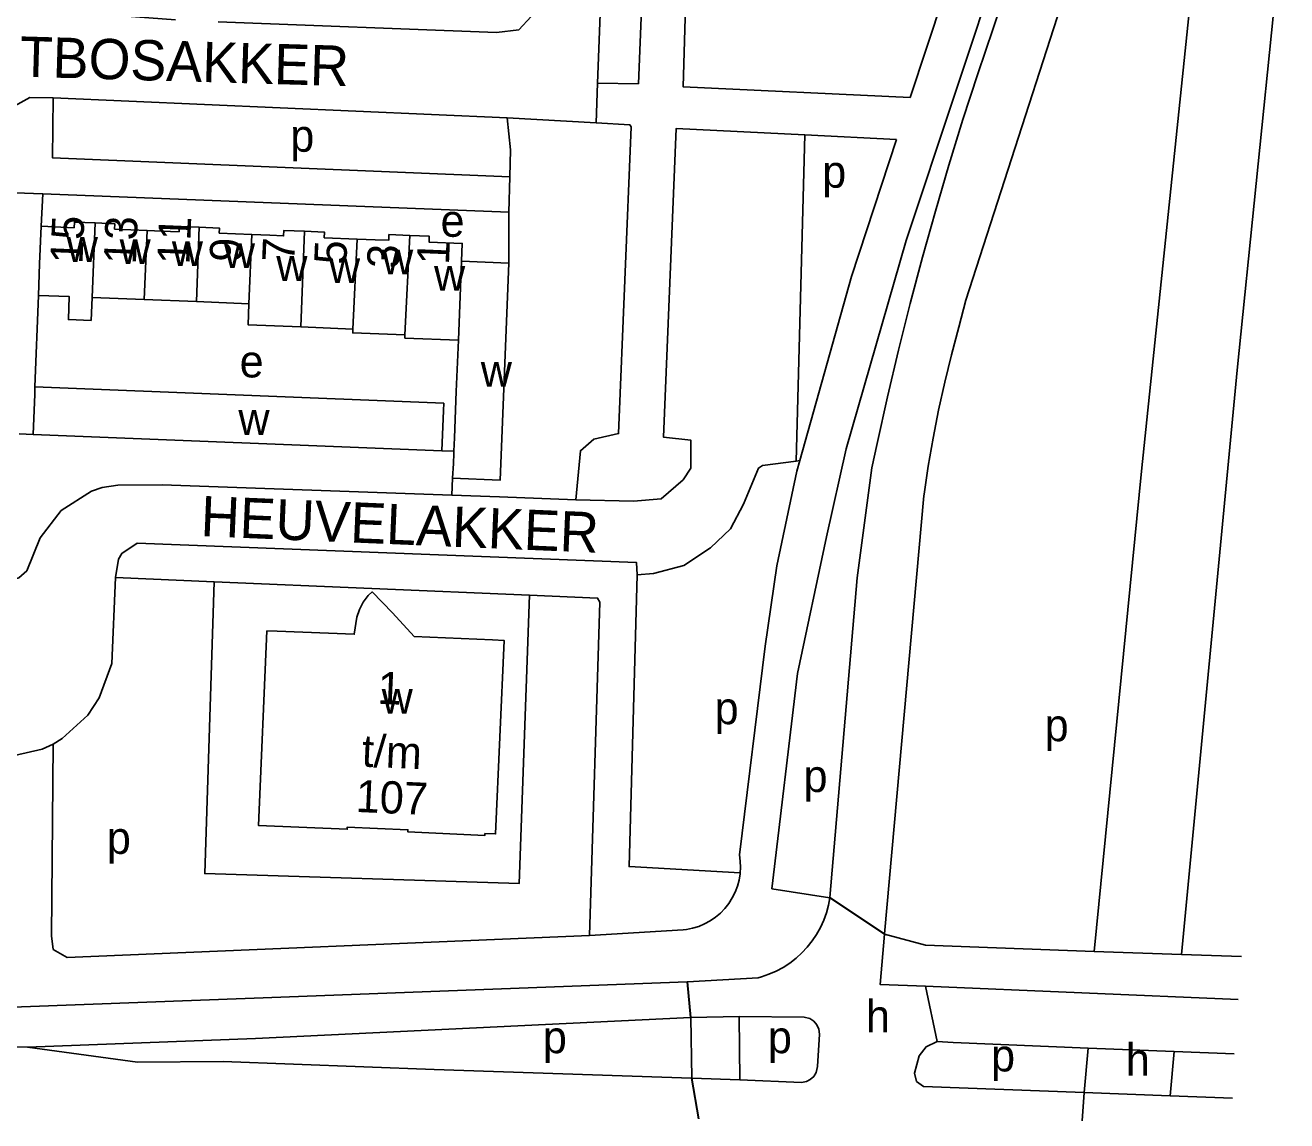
# Model space of a CAD drawing. Extents: x 159675 to 162108, y 386471 to 388472.
# Drawn here: x 161786.5 to 161943, y 386511.2 to 386647.1 of the extents above; entities that cross this region are included whole.
import ezdxf

# ---------------------------------------------------------------- set-up
doc = ezdxf.new("R2010")
doc.units = 0
for name, color, linetype in [('BLT_Basislijn', 7, 'Continuous'), ('BLT_Bebouwing', 7, 'Continuous'), ('BLT_Centroide', 7, 'Continuous'), ('BLT_Huisnummer', 7, 'Continuous'), ('BLT_Huisnummer_ tussenligend', 7, 'Continuous'), ('BLT_Huisnummer_reeks', 7, 'Continuous'), ('BLT_Onderverdeling_panden', 7, 'Continuous'), ('BLT_Straatnaam', 7, 'Continuous'), ('BLT_Vlakafsluiter', 7, 'Continuous')]:
    doc.layers.add(name, color=color, linetype=linetype)

msp = doc.modelspace()

# ---------------------------------------------------------------- linework, layer by layer
at = {"layer": 'BLT_Basislijn'}
for p, q in [((161859.4, 386689.5), (161857.47, 386639.94)), ((161943.04, 386664.85), (161936.89, 386604.32)), ((161904.47, 386662.94), (161896.31, 386638.15)), ((161908.9, 386653.63), (161906.59, 386646.72)), ((161857.33, 386635.03), (161857.47, 386639.94)), ((161846.28, 386635.63), (161789.92, 386638.11)), ((161857.33, 386635.03), (161846.28, 386635.63)), ((161882.16, 386593.06), (161883.24, 386633.54)), ((161894.59, 386632.96), (161883.24, 386633.54)), ((161759.37, 386627.34), (161788.65, 386626.22)), ((161846.48, 386623.96), (161846.61, 386628.31)), ((161788.44, 386622.19), (161788.65, 386626.22)), ((161788.65, 386626.22), (161846.48, 386623.96)), ((161846.5, 386617.63), (161846.48, 386623.96)), ((161787.67, 386602.26), (161788.09, 386613.62)), ((161936.89, 386604.32), (161929.99, 386531.84)), ((161785.72, 386596.45), (161787.43, 386596.36)), ((161838.18, 386594.33), (161839.66, 386594.27)), ((161882.16, 386593.06), (161882.59, 386593.12)), ((161882.59, 386593.12), (161882.22, 386591.81)), ((161839.41, 386588.84), (161839.51, 386590.94)), ((161925.02, 386591.81), (161919.12, 386532.23)), ((161897.99, 386588.74), (161893.13, 386534.42)), ((161797.66, 386578.61), (161809.91, 386578.09)), ((161849.05, 386576.41), (161809.91, 386578.09)), ((161879.13, 386539.98), (161886.32, 386538.87)), ((161868.11, 386534.89), (161856.51, 386534.19)), ((161893.13, 386534.42), (161893.13, 386534.37)), ((161919.12, 386532.23), (161929.99, 386531.84)), ((161929.99, 386531.84), (161937.43, 386531.57)), ((161877.43, 386528.96), (161868.67, 386528.44)), ((161898.2, 386527.9), (161937.02, 386526.27)), ((161869.09, 386524.04), (161875.06, 386524.13)), ((161869.19, 386516.5), (161869.09, 386524.04)), ((161875.14, 386516.27), (161875.06, 386524.13)), ((161773.01, 386520.5), (161786.75, 386520.36)), ((161901.65, 386520.9), (161918.38, 386520.23)), ((161918.38, 386520.23), (161917.91, 386514.7)), ((161918.38, 386520.23), (161929.06, 386519.8)), ((161929.06, 386519.8), (161928.57, 386514.3)), ((161929.06, 386519.8), (161936.5, 386519.51)), ((161875.14, 386516.27), (161869.19, 386516.5)), ((161917.91, 386514.7), (161928.57, 386514.3)), ((161928.57, 386514.3), (161936.29, 386514.01))]:
    msp.add_line(p, q, dxfattribs=at)
for points in [[(161925.02, 386591.81), (161939.22, 386728.77), (161938.38, 386728.77), (161932.65, 386706.72), (161925.87, 386683.19), (161903.2, 386613.02)], [(161857.47, 386639.94), (161862.57, 386639.88), (161864.58, 386689.33)], [(161805.09, 386647.8), (161794.63, 386648.61), (161793.59, 386649.22), (161792.32, 386651.64), (161795.33, 386682.63), (161796.09, 386683.77), (161797.33, 386684.86), (161800.07, 386685.28), (161806.04, 386685.31), (161841.87, 386684), (161847.97, 386683.27), (161849.56, 386681.29), (161849.86, 386679.53), (161849.6, 386649.72), (161849.24, 386648.24), (161847.72, 386646.55), (161844.95, 386646.25), (161810.4, 386647.55)], [(161868.86, 386665.23), (161868.1, 386639.51), (161896.31, 386638.15)], [(161907.79, 386656.55), (161895.78, 386620.43), (161888.37, 386594.57)], [(161906.59, 386646.72), (161904.68, 386641.1), (161902.85, 386635.44), (161901.1, 386629.76), (161899.42, 386624.06), (161897.82, 386618.34), (161896.29, 386612.6), (161894.84, 386606.83), (161893.47, 386601.05), (161892.18, 386595.25), (161891.54, 386592.24)], [(161784.3, 386636.97), (161784.81, 386636.92), (161787.05, 386638.16), (161789.92, 386638.11)], [(161789.92, 386638.11), (161789.83, 386630.69), (161846.61, 386628.31)], [(161846.28, 386635.63), (161846.7, 386631.68), (161846.61, 386628.31)], [(161857.33, 386635.03), (161861.51, 386634.77), (161861.67, 386634.54), (161860.1, 386596.47), (161857.02, 386595.79), (161855.36, 386594.35), (161854.81, 386588.26)], [(161883.24, 386633.54), (161867.27, 386634.34), (161865.66, 386596.04), (161869.09, 386595.65), (161869.09, 386592.17), (161868.12, 386590.72), (161865.39, 386588.36), (161861.95, 386588.1), (161854.81, 386588.26)], [(161894.59, 386632.96), (161889, 386615.98), (161882.59, 386593.12)], [(161903.2, 386613.02), (161902.34, 386609.67), (161901.42, 386606.26), (161900.58, 386602.83), (161899.82, 386599.39), (161899.14, 386595.92), (161898.54, 386592.44), (161898.02, 386588.95), (161897.99, 386588.74)], [(161888.37, 386594.57), (161885.91, 386583.65), (161882.31, 386566.69), (161879.13, 386539.98)], [(161862.43, 386578.93), (161864.43, 386579.13), (161868.19, 386580.09), (161871.52, 386582.3), (161873.99, 386584.67), (161875.62, 386587.72), (161877.49, 386592.19), (161877.97, 386592.51), (161882.16, 386593.06)], [(161882.22, 386591.81), (161879.76, 386580.05), (161878.28, 386570.09), (161875.1, 386544.22)], [(161886.33, 386538.93), (161889.72, 386578.57), (161891.54, 386592.24)], [(161784.98, 386578.37), (161785.65, 386578.59), (161786.67, 386579.46), (161788.32, 386583.52), (161790.93, 386586.93), (161794.67, 386589.31), (161796, 386589.77), (161797.94, 386590.09), (161803.45, 386590.12), (161839.41, 386588.84)], [(161839.41, 386588.84), (161845.32, 386588.61), (161854.81, 386588.26)], [(161862.43, 386578.93), (161862.31, 386580.49), (161800.36, 386582.87), (161798.46, 386581.6), (161798.03, 386580.87), (161797.66, 386578.61)], [(161789.91, 386557.93), (161791.05, 386558.63), (161794.21, 386561.52), (161795.65, 386563.68), (161797.19, 386567.95), (161797.66, 386578.61)], [(161862.43, 386578.93), (161861.41, 386542.75), (161875.2, 386541.98)], [(161849.05, 386576.41), (161847.75, 386540.63), (161808.74, 386541.87), (161809.91, 386578.09)], [(161849.05, 386576.41), (161857.49, 386576.06), (161857.79, 386575.56), (161856.51, 386534.19)], [(161789.91, 386557.93), (161788.58, 386557.31), (161785.14, 386556.53)], [(161789.91, 386557.93), (161789.71, 386534.16), (161789.91, 386532.47), (161791.67, 386531.47), (161856.51, 386534.19)], [(161875.1, 386544.22), (161875.21, 386543.43), (161875.24, 386542.64), (161875.2, 386541.98)], [(161875.2, 386541.98), (161875.19, 386541.85), (161875.06, 386541.06), (161874.85, 386540.3), (161874.57, 386539.56), (161874.21, 386538.85), (161873.79, 386538.18), (161873.29, 386537.55), (161872.74, 386536.98), (161872.14, 386536.47), (161871.48, 386536.02), (161870.78, 386535.64), (161870.05, 386535.33), (161869.29, 386535.1), (161868.52, 386534.94), (161868.11, 386534.89)], [(161886.32, 386538.87), (161886.15, 386537.96), (161885.9, 386537.01), (161885.57, 386536.08), (161885.16, 386535.19), (161884.68, 386534.33), (161884.14, 386533.52), (161883.53, 386532.75), (161882.86, 386532.03), (161882.13, 386531.37), (161881.35, 386530.77), (161880.53, 386530.24), (161879.67, 386529.78), (161878.77, 386529.39), (161877.84, 386529.07), (161877.43, 386528.96)], [(161886.32, 386538.87), (161886.33, 386538.93)], [(161893.13, 386534.37), (161892.57, 386528.13), (161898.2, 386527.9)], [(161893.13, 386534.37), (161898.2, 386532.98), (161919.12, 386532.23)], [(161609.58, 386522.22), (161613.35, 386522.37), (161623.99, 386521.31), (161637.37, 386520.22), (161715.37, 386522.87), (161751.55, 386524.05), (161814.86, 386526.42), (161868.62, 386528.44)], [(161868.62, 386528.44), (161868.67, 386528.44)], [(161786.75, 386520.36), (161815.05, 386521.43), (161869.04, 386524.03)], [(161869.04, 386524.03), (161869.09, 386524.04)], [(161875.06, 386524.13), (161883.12, 386524.05), (161883.86, 386523.88), (161884.35, 386523.56), (161884.73, 386523.11), (161884.96, 386522.58), (161885.03, 386521.97), (161884.79, 386517.96), (161884.64, 386517.21), (161884.34, 386516.7), (161883.89, 386516.32), (161883.42, 386516.09), (161882.81, 386515.97), (161875.14, 386516.27)], [(161899.66, 386521.03), (161898.28, 386520.38), (161897.41, 386519.28), (161896.83, 386517.13), (161897.08, 386516.1), (161897.93, 386515.46), (161917.91, 386514.7)], [(161901.65, 386520.9), (161899.66, 386521.03)], [(161786.75, 386520.36), (161800.41, 386518.49), (161811.03, 386518.55), (161837.23, 386517.55), (161869.14, 386516.51)], [(161869.14, 386516.51), (161869.19, 386516.5)]]:
    msp.add_lwpolyline(points, dxfattribs=at)
at = {"layer": 'BLT_Bebouwing'}
for p, q in [((161840.62, 386617.87), (161846.5, 386617.63)), ((161801.24, 386613.1), (161794.75, 386613.36)), ((161807.7, 386612.85), (161801.24, 386613.1)), ((161814.23, 386612.59), (161807.7, 386612.85)), ((161827.12, 386609.44), (161820.66, 386609.7)), ((161838.18, 386594.33), (161787.43, 386596.36)), ((161839.65, 386594.02), (161839.66, 386594.27))]:
    msp.add_line(p, q, dxfattribs=at)
for points in [[(161788.44, 386622.19), (161788.25, 386617.52), (161788.09, 386613.62)], [(161788.44, 386622.19), (161792.53, 386622.02), (161792.56, 386622.7), (161795.12, 386622.6)], [(161795.12, 386622.6), (161797.58, 386622.5), (161797.55, 386621.85), (161801.59, 386621.68)], [(161801.59, 386621.68), (161803.43, 386621.6), (161805.56, 386621.52), (161805.59, 386622.17), (161808.06, 386622.07)], [(161808.06, 386622.07), (161810.56, 386621.97), (161810.54, 386621.34), (161814.57, 386621.16)], [(161814.57, 386621.16), (161816.82, 386621.07), (161818.53, 386620.99), (161818.56, 386621.68), (161821.13, 386621.58)], [(161821.13, 386621.58), (161823.6, 386621.48), (161823.57, 386620.76), (161827.64, 386620.61)], [(161827.64, 386620.61), (161829.88, 386620.52), (161831.57, 386620.45), (161831.59, 386621.16), (161834.2, 386621.05)], [(161834.2, 386621.05), (161836.61, 386620.96), (161836.58, 386620.24), (161840.71, 386620.07), (161840.62, 386617.87)], [(161846.5, 386617.63), (161845.41, 386590.7), (161839.51, 386590.94)], [(161794.75, 386613.36), (161794.63, 386610.51), (161791.82, 386610.62), (161791.93, 386613.47), (161788.09, 386613.62)], [(161820.66, 386609.7), (161814.13, 386609.95), (161814.23, 386612.59)], [(161833.59, 386608.71), (161827.1, 386608.97), (161827.12, 386609.44)], [(161840.23, 386608.06), (161833.58, 386608.32), (161833.59, 386608.71)], [(161839.66, 386594.27), (161839.73, 386595.93), (161839.96, 386601.71), (161840.23, 386608.06)], [(161787.43, 386596.36), (161787.64, 386601.36), (161787.67, 386602.26)], [(161787.67, 386602.26), (161838.41, 386600.23), (161838.38, 386599.33), (161838.18, 386594.33)], [(161839.51, 386590.94), (161839.6, 386592.76), (161839.65, 386594.02)]]:
    msp.add_lwpolyline(points, dxfattribs=at)
msp.add_lwpolyline([(161816.46, 386571.98), (161817.73, 386571.95), (161827.3, 386571.58), (161827.61, 386573.68), (161827.93, 386574.66), (161828.41, 386575.56), (161829.04, 386576.37), (161829.54, 386576.82), (161832.03, 386574.24), (161834.72, 386571.31), (161844.47, 386570.87), (161845.89, 386570.81), (161844.83, 386546.79), (161843.52, 386546.85), (161843.51, 386546.62), (161833.95, 386547.04), (161833.96, 386547.31), (161826.43, 386547.64), (161826.42, 386547.37), (161815.4, 386547.86)], close=True, dxfattribs=at)
at = {"layer": 'BLT_Onderverdeling_panden'}
for p, q in [((161794.75, 386613.36), (161795.12, 386622.6)), ((161801.24, 386613.1), (161801.59, 386621.68)), ((161807.7, 386612.85), (161808.06, 386622.07)), ((161814.23, 386612.59), (161814.57, 386621.16)), ((161820.66, 386609.7), (161821.13, 386621.58)), ((161833.59, 386608.71), (161834.2, 386621.05)), ((161827.12, 386609.44), (161827.64, 386620.61)), ((161840.62, 386617.87), (161840.23, 386608.06))]:
    msp.add_line(p, q, dxfattribs=at)
at = {"layer": 'BLT_Vlakafsluiter'}
for p, q in [((161886.32, 386538.87), (161893.13, 386534.37)), ((161886.33, 386538.93), (161893.13, 386534.42)), ((161868.62, 386528.44), (161869.04, 386524.03)), ((161868.67, 386528.44), (161869.09, 386524.04)), ((161898.2, 386527.9), (161899.66, 386521.03)), ((161869.14, 386516.51), (161870.02, 386511.43)), ((161869.19, 386516.5), (161870.07, 386511.43)), ((161917.63, 386511.21), (161917.91, 386514.7))]:
    msp.add_line(p, q, dxfattribs=at)

# ---------------------------------------------------------------- texts
at = {"layer": 'BLT_Centroide'}
for s, p in [('p', (161819.36, 386631.44)), ('p', (161885.38, 386626.98)), ('e', (161838.01, 386620.89)), ('w', (161791.61, 386617.77)), ('w', (161798.17, 386617.52)), ('w', (161804.66, 386617.27)), ('w', (161811.12, 386617.02)), ('w', (161830.75, 386616.22)), ('w', (161817.62, 386615.42)), ('w', (161824.16, 386615.16)), ('w', (161837.2, 386614.2)), ('e', (161813.07, 386603.44)), ('w', (161843, 386602.28)), ('w', (161812.92, 386596.31)), ('w', (161830.7, 386561.72)), ('p', (161872.03, 386560.41)), ('p', (161912.99, 386558.3)), ('p', (161883.06, 386552)), ('p', (161796.59, 386544.32)), ('h', (161890.81, 386522.2)), ('p', (161850.71, 386519.59)), ('p', (161878.64, 386519.59)), ('p', (161906.34, 386517.33)), ('h', (161923.06, 386516.8))]:
    msp.add_text(s, height=4, dxfattribs=at).set_placement(p)
at = {"layer": 'BLT_Huisnummer'}
for s, p in [('15', (161793.56, 386617.48)), ('9', (161813.32, 386617.7)), ('5', (161826.31, 386617.4)), ('1', (161839.05, 386617.37))]:
    msp.add_text(s, height=4, rotation=87.6224, dxfattribs=at).set_placement(p)
at = {"layer": 'BLT_Huisnummer_ tussenligend'}
for s, p in [('13', (161800.19, 386617.43)), ('11', (161806.83, 386617.41)), ('7', (161819.85, 386617.71)), ('3', (161832.86, 386616.91))]:
    msp.add_text(s, height=4, rotation=87.6224, dxfattribs=at).set_placement(p)
at = {"layer": 'BLT_Huisnummer_reeks'}
for s, rotation, p in [('1', 357.4727, (161830.13, 386562.96)), ('t/m', 357.4733, (161828.18, 386555.16)), ('107', 357.4738, (161827.42, 386549.53))]:
    msp.add_text(s, height=4, rotation=rotation, dxfattribs=at).set_placement(p)
at = {"layer": 'BLT_Straatnaam'}
for s, rotation, p in [('HULSTBOSAKKER', 358.3318, (161767.89, 386641.28)), ('HEUVELAKKER', 357.599, (161808.17, 386583.75))]:
    msp.add_text(s, height=4.9999, rotation=rotation, dxfattribs=at).set_placement(p)

doc.saveas('drawing.dxf')
